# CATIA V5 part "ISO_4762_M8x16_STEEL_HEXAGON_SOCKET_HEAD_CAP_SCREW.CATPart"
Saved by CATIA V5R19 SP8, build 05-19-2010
Part number: ISO 4762 SCREW M8x16 STEEL HEXAGON SOCKET HEAD CAP
Nomenclature: 23
Publications: "Mating Face", "Axis"
Bounding box of the stored display mesh (mm): x -16 to 8, y -6.5 to 6.5, z -6.49 to 6.49
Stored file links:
  C:\Users\rphgr\Desktop\0_Tapis_TC520B_vitesse\ISO_4762_M8x16_STEEL_HEXAGON_SOCKET_HEAD_CAP_SCREW.CATPart
  D:\Programmes\DassaultSysteme\win_b64\startup\components\MechanicalStandardParts\EN_Standards\Design_Tables\EN_ISO_4762_HEXAGON_SOCKET_HEAD_CAP_SCREW.txt
  C:\Program Files\Dassault Systemes\B19\win_b64\startup\components\MechanicalStandardParts\ISO_Standards\Design_Tables\ISO_4762_HEXAGON_SOCKET_HEAD_CAP_SCREW.txt
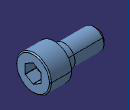
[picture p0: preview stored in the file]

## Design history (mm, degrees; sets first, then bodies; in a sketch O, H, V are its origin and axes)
Parameters
  d_dia = 8 mm
  l_nom = 16 mm
  k_head_depth_max = 8 mm
  s_nom = 6 mm
  r_min = 0.4 mm
  ds_max = 8 mm
  e = 6.863 mm
  t_min = 4 mm
  p_pitch = 1.25 mm
  Threading = 12.25 mm
  dk_max = 13 mm
Body1 "PartBody" (main body)
  Sketch1 on yz-plane, origin (0, 0, 0), H (0, 1, 0), V (0, 0, 1)
    circle A1 centre (0, 0) radius 6.5
    radius A1 = 6.5 {= dk_max /2}
  Pad1: profile Sketch1, direction (1, 0, 0), length 8 {= k_head_depth_max}
  Fillet1: radius 0.4 {= r_min}, on edge [face of Pad1 | face of Pad1]
  Body2
    Sketch2 on face of Pad1, origin (8, 0, 0), H (0, 1, 0), V (0, 0, 1)
      point P1 (3, -1.7321)
      point P2 (3, 1.7321)
      point P3 (0, 3.4641)
      point P4 (-3, 1.7321)
      point P5 (-3, -1.7321)
      point P6 (0, -3.4641)
      point P7 (3, 0)
      line L1 (3, -1.7321) -> (3, 1.7321)
      line L2 (3, 1.7321) -> (0, 3.4641)
      line L3 (0, 3.4641) -> (-3, 1.7321)
      line L4 (-3, 1.7321) -> (-3, -1.7321)
      line L5 (-3, -1.7321) -> (0, -3.4641)
      line L6 (0, -3.4641) -> (3, -1.7321)
      construction line L7 (0, 0) -> (3, 0)
      construction circle A1 centre (0, 0) radius 3.4641
      construction arc A2 centre (-3, -1.7321) radius 3.4641 from (-3, 1.7321) to (0, -3.4641) cw
      construction arc A3 centre (3, 1.7321) radius 3.4641 from (0, 3.4641) to (3, -1.7321) ccw
      point P8 (-3, -1.7321)
      point P9 (3, 1.7321)
      distance L1 L4 = 6 {= s_nom}
      horizontal: L7 H
      coincidence: A1 P1, A1 P2, A1 P3, A1 P4, A1 P5, A1 P6, A2 P4, A2 P6, A2 O, P8 P5, A3 P3, A3 P1, A3 O, P9 P2
      midpoint: P7 L1
    Pad2: profile Sketch2, direction (-1, 0, 0), length 5.9778 {= t_min +(e /3.47)}
    Body3
      Sketch3 on zx-plane, origin (0, 0, 0), H (-1, 0, 0), V (0, 0, 1)
        point P1 (-2.0188, 0)
        line L1 (-2.0188, 0) -> (-4, 3.4315)
        line L2 (-4, 3.4315) -> (-8, 3.4315)
        line L3 (-8, 3.4315) -> (-8, 0)
        axis line L4 (-46.2384, 0) -> (26.3409, 0)
        reference projected line E1 (-8, -6.9227) -> (-8, 6.9227) from edge [face of Pad2 | face of Pad2]
        length L2 = 4 {= t_min}
        angle L1 L4 = 60
        distance L2 L4 = 3.4315 {= e /2}
        horizontal: L2 H, L4 H
        perpendicularity: L3 L2
        fix: L4
        coincidence: L3 E1, P1 L4
      Shaft1: profile Sketch3, axis Sketch3.L4, angle 360
    Intersect1: tool Body3
  Remove1: tool Body2
  Sketch4 on xy-plane, origin (0, 0, 0), H (1, 0, 0), V (0, 1, 0)
    line L1 (0, 0) -> (0, 4)
    line L2 (0, 4) -> (-3.75, 4)
    line L3 (-3.75, 4) -> (-3.75, 3.9024)
    line L4 (-3.75, 3.9024) -> (-16, 3.9024)
    line L5 (-16, 3.9024) -> (-16, 0)
    axis line L6 (-192.3446, 0) -> (99.1594, 0)
    distance L5 L1 = 16 {= l_nom}
    distance L3 L5 = 12.25 {= Threading}
    distance L2 L6 = 4 {= ds_max /2}
    distance L4 L6 = 3.9024 {= d_dia /2.05}
    vertical: L1 V, L3 V, L5 V
    horizontal: L2 H, L4 H, L6 H
    fix: L6
  Shaft2: profile Sketch4, axis Sketch4.L6, angle 360
  Fillet2: radius 0.4 {= r_min}, on edge [face of Shaft2 | face of Pad1]
  Chamfer1: length 1.25 {= p_pitch}, angle 45, on edge [face of Shaft2 | face of Shaft2]
  Thread1: diameter 7.8049 {= d_dia /1.025}, depth 12.25 {= Threading}, pitch 1, on face of Shaft2, from face of Shaft2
